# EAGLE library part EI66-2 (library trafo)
TRANSFORMER 1 primary winding, 2 secondary windings, mounting holes ERA
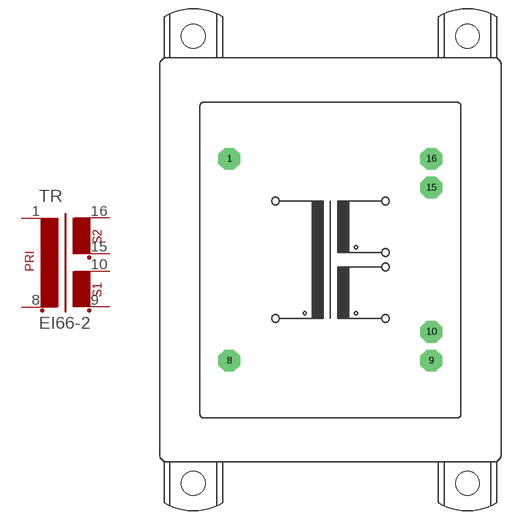
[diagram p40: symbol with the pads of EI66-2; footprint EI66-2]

Designator prefix TR

## EI66-2  [EI66-2]
1  1  pas
8  2  pas
9  3  pas
10  4  pas
15  5  pas
16  6  pas

## Footprint EI66-2 (pad centres in mm)
TRANSFORMER 1 primary winding, 2 secondary windings, mounting holes
drill 1.194 pad 3.81 octagon: 1 -17.501,17.501; 8 -17.501,-17.501; 9 17.501,-17.501; 10 17.501,-12.497; 15 17.501,12.497; 16 17.501,17.501
hole 4.115 at -23.749,-38.76
hole 4.115 at -23.749,38.76
hole 4.115 at 23.749,-38.76
hole 4.115 at 23.749,38.76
